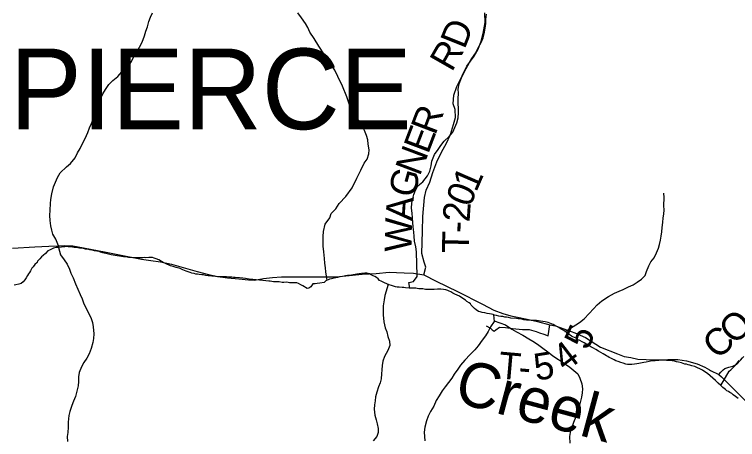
# Model space of a CAD drawing. Extents: x 1310247 to 1664935, y 235267 to 584339.
# Drawn here: x 1460622 to 1468683, y 371649 to 376395 of the extents above; entities that cross this region are included whole.
import ezdxf

# ---------------------------------------------------------------- set-up
doc = ezdxf.new("R2010")
doc.units = 0
for name, color, linetype in [('GM_X_Minor_River', 7, 'Continuous'), ('GM_X_Minor_River_Text', 7, 'Continuous'), ('GM_X_State_Route', 7, 'Continuous'), ('GM_X_Township_Road', 7, 'Continuous'), ('GM_X_Township_Road_Text', 7, 'Continuous'), ('GM_X_Township_Text', 7, 'Continuous')]:
    doc.layers.add(name, color=color, linetype=linetype)

msp = doc.modelspace()

# ---------------------------------------------------------------- linework, layer by layer
at = {"layer": 'GM_X_Minor_River'}
for points in [[(1461120.8, 373794.9), (1461082.9, 373885.9), (1461049.7, 373942.7), (1461036.4, 373987.1), (1461025.2, 374035.5), (1461020.2, 374095.9), (1461017.1, 374150.2), (1461018.1, 374210.4), (1461023.3, 374282.6), (1461026.1, 374328.8), (1461037.2, 374390.9), (1461058.6, 374470.8), (1461100.5, 374574.5), (1461131.5, 374626.2), (1461202.9, 374693.3), (1461247.7, 374730.6), (1461296.9, 374794), (1461326, 374849.8), (1461352.9, 374899.5), (1461384.1, 374961.2), (1461409, 375011), (1461440.2, 375076.8), (1461459.1, 375128.7), (1461480.1, 375178.5), (1461501.1, 375238.4), (1461526.5, 375312.3), (1461585.2, 375459.9), (1461608.1, 375507.7), (1461635, 375557.4), (1461674, 375611), (1461719, 375656.4), (1461773.9, 375703.6), (1461835.4, 375776.9), (1461888.3, 375820.1), (1461923.2, 375863.7), (1461946.1, 375911.5), (1461977, 375961.2), (1462014.3, 376028.8), (1462045.4, 376086.5), (1462070.6, 376156.4), (1462087.5, 376206.3), (1462106.5, 376258.2), (1462119.5, 376316.2), (1462136.4, 376366.1), (1462159.3, 376413.9)], [(1464106.3, 373426.6), (1464093.8, 373521.9), (1464088.6, 373566.1), (1464081.4, 373618.5), (1464076.2, 373668.8), (1464069.5, 373743.2), (1464064.5, 373807.6), (1464063.5, 373865.9), (1464064.3, 373914.1), (1464067.3, 373970.2), (1464086.7, 374052.3), (1464138.1, 374125.7), (1464151, 374171.6), (1464206.1, 374224.9), (1464243.2, 374282.5), (1464314.8, 374363.6), (1464386.7, 374460.8), (1464438.6, 374566.3), (1464484.4, 374657.9), (1464521.8, 374733.6), (1464554.6, 374779.2), (1464571.7, 374837.2), (1464574.5, 374883.3), (1464565.5, 374947.7), (1464560.3, 374996), (1464547.1, 375044.5), (1464523.9, 375099.1), (1464494.8, 375157.9), (1464455.6, 375212.8), (1464412.4, 375269.8), (1464381.3, 375334.6), (1464358.1, 375387.2), (1464327.5, 375476.1), (1464279.3, 375593.5), (1464224.9, 375700.9), (1464192, 375773.8), (1464148.9, 375838.8), (1464121.6, 375885.5), (1464070.6, 375954.7), (1464013.8, 376040), (1463963.1, 376125.3), (1463916.1, 376198.4), (1463892.9, 376249), (1463867.5, 376293.7), (1463822.5, 376358.7), (1463779.2, 376413.7)], [(1465030.5, 373340.8), (1465017.2, 373403.3), (1465071.6, 373414.4), (1465110.7, 373469.9), (1465109.5, 373516.1), (1465108.5, 373574.4), (1465105.8, 373652.8), (1465104.6, 373701), (1465103.3, 373745.2), (1465096.2, 373799.6), (1465083.2, 373864.1), (1465076.1, 373918.4), (1465072.9, 373964.7), (1465065.9, 374025.1), (1465062.6, 374071.3), (1465057.5, 374123.6), (1465054.4, 374177.9), (1465049.3, 374232.3), (1465050.2, 374288.5), (1465061.1, 374338.5), (1465073.9, 374384.5), (1465092.8, 374432.3), (1465119.7, 374480.1), (1465174.7, 374527.3), (1465226, 374594.7), (1465251, 374646.5), (1465268, 374706.5), (1465274.9, 374756.6), (1465304.3, 374832.4), (1465343.4, 374887.9), (1465376.2, 374933.5), (1465413.1, 374979.1), (1465468.2, 375032.4), (1465507.2, 375079.9), (1465532.2, 375133.7), (1465555.1, 375183.5), (1465568.1, 375239.5), (1465573.1, 375297.7), (1465571.9, 375345.9), (1465568.8, 375400.2), (1465567.7, 375452.4), (1465570.7, 375514.6), (1465569.5, 375560.9), (1465580.5, 375618.9), (1465605.7, 375686.8), (1465630.7, 375740.6), (1465655.7, 375790.3), (1465695, 375860), (1465721.8, 375903.7), (1465765, 375967.2), (1465790.1, 376023), (1465823.2, 376082.7), (1465846.1, 376132.5), (1465861.2, 376196.5), (1465868, 376242.6), (1465874.9, 376294.7), (1465877.7, 376338.8), (1465884.7, 376396.9)], [(1466758.8, 372855.4), (1466811.1, 372885.8), (1466922.7, 372956.1), (1466971.6, 372997.5), (1467028.8, 373054.7), (1467077.9, 373108.1), (1467118.7, 373151.6), (1467169.7, 373198.9), (1467244.8, 373247.8), (1467309.6, 373282.8), (1467362.2, 373304), (1467406.7, 373325.3), (1467467.4, 373352.4), (1467518, 373377.6), (1467562.6, 373404.9), (1467611.4, 373438.2), (1467652.2, 373481.7), (1467669, 373525.6), (1467694.2, 373587.4), (1467717, 373633.2), (1467751.9, 373676.8), (1467778.9, 373732.5), (1467799.9, 373784.4), (1467812.6, 373828.4), (1467825.5, 373874.3), (1467832.2, 373918.4), (1467837, 373966.5), (1467843.9, 374014.6), (1467848.8, 374070.8), (1467853.7, 374122.9), (1467860.5, 374167), (1467863.3, 374213.1), (1467862, 374257.3), (1467863.6, 374351.7), (1467862.4, 374400)], [(1463626.1, 373403.5), (1463606.1, 373403.9), (1463574, 373408.4), (1463507.8, 373411.6), (1463473.8, 373416.2), (1463457.8, 373418.5), (1463391.7, 373425.7), (1463353.6, 373428.4), (1463317.5, 373433), (1463279.4, 373435.7), (1463239.3, 373440.4), (1463217.3, 373442.8), (1463197.3, 373447.2), (1463169.3, 373451.7), (1463131.2, 373454.3), (1463083.1, 373459.2), (1463065, 373459.5), (1463045, 373461.9), (1463006.9, 373462.5), (1462984.8, 373465), (1462884.5, 373466.7), (1462862.4, 373469.1), (1462840.4, 373471.5), (1462820.4, 373473.8), (1462782.3, 373478.5), (1462756.2, 373481), (1462728.3, 373487.5), (1462710.2, 373487.8), (1462682.2, 373492.3), (1462662.1, 373494.7), (1462644.1, 373497), (1462626.1, 373501.3), (1462598.1, 373507.9), (1462582.1, 373512.2), (1462558.2, 373522.6), (1462534.2, 373529.1), (1462516.3, 373537.4), (1462500.4, 373543.7), (1462476.5, 373556.2), (1462456.5, 373560.6), (1462440.5, 373566.9), (1462424.5, 373571.2), (1462390.6, 373581.8), (1462360.6, 373588.3), (1462344.6, 373594.7), (1462326.7, 373603), (1462304.8, 373615.4), (1462280.9, 373623.9), (1462259, 373636.3), (1462231.3, 373656.9), (1462201.3, 373667.5), (1462179.4, 373675.9), (1462159.4, 373680.2), (1462141.4, 373682.6), (1462119.3, 373681), (1462087.1, 373679.5), (1462071.1, 373679.8), (1462053, 373678.1), (1462008.8, 373678.9), (1461986.7, 373677.2), (1461940.6, 373678.1), (1461924.5, 373680.3), (1461892.5, 373682.9), (1461860.4, 373687.5), (1461838.4, 373689.9), (1461814.3, 373692.3), (1461766.3, 373701.2), (1461744.3, 373703.6), (1461720.3, 373708), (1461700.3, 373712.4), (1461656.2, 373721.2), (1461608.3, 373734.1), (1461582.3, 373740.6), (1461564.3, 373746.9), (1461538.3, 373751.4), (1461514.3, 373755.8), (1461486.3, 373762.3), (1461460.3, 373766.8), (1461436.3, 373773.3), (1461414.3, 373775.6), (1461390.3, 373782.1), (1461346.2, 373786.9), (1461326.2, 373789.2), (1461302.1, 373791.7), (1461286.1, 373794), (1461268.1, 373798.3), (1461238, 373800.8), (1461222, 373801.1), (1461206, 373803.4), (1461183.9, 373801.8), (1461145.6, 373796.4), (1461119.5, 373794.9), (1461085.3, 373791.5), (1461057.1, 373783.9), (1461026.8, 373772.4), (1461010.6, 373764.6), (1460994.4, 373754.9), (1460965.8, 373725.2), (1460943.3, 373703.5), (1460923, 373687.8), (1460904.6, 373668.1)], [(1461113.7, 373794.3), (1461134.1, 373710.2), (1461177.4, 373657.3), (1461208.7, 373606.5), (1461233.8, 373551.8), (1461251.2, 373507.3), (1461274.3, 373452.7), (1461303.3, 373385.9), (1461326.4, 373329.3), (1461353.5, 373268.5), (1461376.8, 373219.9), (1461390.1, 373175.5), (1461442.5, 373066.1), (1461471.6, 373011.4), (1461490.8, 372954.8), (1461500, 372906.4), (1461506.7, 372830), (1461503.8, 372777.8), (1461497.1, 372733.8), (1461477.9, 372665.8), (1461454.8, 372605.9), (1461427.9, 372558.2), (1461394.9, 372508.6), (1461368.1, 372462.8), (1461342.9, 372399), (1461336.1, 372350.9), (1461337.2, 372296.7), (1461332.4, 372250.5), (1461321.5, 372202.5), (1461300.2, 372128.6), (1461281.3, 372076.7), (1461262.4, 372030.8), (1461239.2, 371960.9), (1461226.4, 371917), (1461219.1, 371842.8), (1461220.2, 371788.5), (1461215.1, 371726.3), (1461210.4, 371682.2), (1461213.5, 371628)], [(1460904.6, 373668.1), (1460880.1, 373642.4), (1460875.8, 373626.4), (1460847.3, 373602.8), (1460830.8, 373579), (1460816.5, 373561.2), (1460799.9, 373533.3), (1460789.6, 373515.4), (1460777.3, 373497.6), (1460766.9, 373479.7), (1460750.4, 373453.8), (1460736, 373432), (1460717.6, 373410.2), (1460697.2, 373392.5), (1460668.9, 373383), (1460636.7, 373377.5), (1460618.6, 373371.8)], [(1466257, 372995.9), (1466238.9, 372998.2), (1466216.9, 373000.6), (1466156.8, 373005.7), (1466128.7, 373010.2), (1466106.7, 373014.6), (1466086.7, 373017), (1466066.7, 373021.3), (1466044.6, 373023.7), (1466020.6, 373028.2), (1465996.7, 373034.6), (1465974.6, 373039), (1465956.7, 373043.4), (1465940.7, 373047.6), (1465918.7, 373052), (1465892.6, 373056.5), (1465864.6, 373063), (1465836.6, 373067.6), (1465812.6, 373074), (1465794.7, 373080.3), (1465768.9, 373098.9), (1465751.1, 373113.2), (1465731.3, 373131.7), (1465713.5, 373148), (1465705.8, 373164.2), (1465689.9, 373174.6), (1465664.1, 373191.1), (1465648.2, 373205.4), (1465630.4, 373217.8), (1465582.7, 373248.8), (1465531, 373273.8), (1465509.1, 373284.2), (1465487.2, 373296.6), (1465467.3, 373307), (1465451.3, 373313.3), (1465431.4, 373319.7), (1465405.3, 373324.2), (1465375.3, 373326.7), (1465337.1, 373327.4), (1465301, 373326), (1465268.8, 373324.5), (1465242.7, 373323), (1465226.7, 373323.3), (1465204.6, 373325.7), (1465172.6, 373330.2), (1465150.5, 373330.6), (1465128.5, 373333), (1465110.4, 373335.4), (1465094.4, 373337.6), (1465076.4, 373338), (1465058.3, 373340.3), (1465020.2, 373341), (1464982.1, 373343.6), (1464964.1, 373346), (1464944, 373346.3), (1464909.9, 373348.9), (1464887.9, 373351.3), (1464867.9, 373355.7), (1464826, 373368.5), (1464800, 373376.9), (1464748.2, 373397.9), (1464730.2, 373406.3), (1464708.3, 373416.7), (1464692.4, 373425), (1464676.7, 373443.4), (1464658.9, 373459.8), (1464640.9, 373468.1), (1464621.1, 373478.5), (1464599.1, 373488.9), (1464581.3, 373499.3), (1464551.3, 373507.8), (1464529.2, 373506.2), (1464491, 373502.9), (1464438.6, 373493.7), (1464380.3, 373484.7), (1464336, 373479.5), (1464311.9, 373475.9), (1464295.7, 373472.1), (1464277.7, 373470.5), (1464247.4, 373464.9), (1464221.2, 373457.4), (1464187, 373449.9), (1464156.7, 373442.4), (1464134.6, 373438.8), (1464094.2, 373421.4), (1464075.8, 373403.7), (1464025.5, 373394.5), (1463997.3, 373391), (1463973.1, 373387.4), (1463947.1, 373387.8), (1463924.4, 373354.1), (1463902.1, 373338.4), (1463885.9, 373334.7), (1463836.3, 373365.7), (1463814.4, 373376.1), (1463786.6, 373392.7), (1463770.6, 373397), (1463724.4, 373399.8), (1463688.3, 373400.4), (1463656.3, 373405), (1463626.1, 373403.5)], [(1464787.7, 373381.9), (1464751.8, 373257.3), (1464742.9, 373207.2), (1464733.8, 373143.1), (1464730.9, 373090.9), (1464732.1, 373040.7), (1464738.8, 372962.2), (1464753.8, 372895.7), (1464771.1, 372851.2), (1464784.2, 372798.7), (1464803.4, 372746.2), (1464804.6, 372698), (1464785.6, 372644.1), (1464748.4, 372576.4), (1464727.4, 372524.6), (1464722.6, 372474.4), (1464717.8, 372428.3), (1464715, 372382.2), (1464708.1, 372328.1), (1464697.3, 372284), (1464680.5, 372238.1), (1464661.4, 372178.2), (1464646.4, 372126.3), (1464641.7, 372080.1), (1464636.9, 372036), (1464630.1, 371990), (1464639, 371921.5), (1464654.2, 371871), (1464665.5, 371824.6), (1464676.7, 371774.2), (1464675.9, 371728), (1464661.1, 371684.1), (1464620.1, 371634.6)], [(1465961.6, 373042.2), (1465969.4, 372966.8), (1465930.3, 372907.2), (1465901.3, 372855.5), (1465872.4, 372805.8), (1465837.4, 372758.2), (1465790.2, 372694.8), (1465755.3, 372651.2), (1465702.2, 372597.9), (1465643, 372536.7), (1465593.8, 372479.3), (1465563, 372433.6), (1465521.9, 372378.1), (1465497.1, 372334.3), (1465462.1, 372284.7), (1465423.2, 372239.2), (1465388.3, 372191.6), (1465357.2, 372135.9), (1465324.2, 372084.3), (1465295.1, 372022.5), (1465260, 371962.9), (1465233, 371909.1), (1465216.1, 371859.2), (1465196.8, 371789.2), (1465189.8, 371731.1), (1465191, 371682.9), (1465198.2, 371634.5)], [(1468688.9, 372105.7), (1468661.3, 372130.3), (1468635.5, 372148.8), (1468617.6, 372163.2), (1468597.7, 372173.6), (1468581.9, 372183.9), (1468564, 372194.3), (1468548.1, 372206.6), (1468520.4, 372231.2), (1468494.7, 372253.8), (1468467.1, 372280.3), (1468435.4, 372309), (1468405.8, 372335.6), (1468346.4, 372384.9), (1468316.6, 372405.5), (1468290.8, 372422), (1468261, 372438.6), (1468235.1, 372451.1), (1468205.2, 372463.7), (1468173.2, 372472.3), (1468151.2, 372478.7), (1468131.2, 372483.1), (1468113.3, 372489.4), (1468095.2, 372491.7), (1468059.4, 372506.4), (1468025.3, 372513), (1468003.3, 372517.5), (1467979.4, 372523.9), (1467955.3, 372528.3), (1467925.3, 372530.9), (1467891.2, 372531.5), (1467857.1, 372534.1), (1467831, 372534.5), (1467806.9, 372532.9), (1467762.7, 372529.7), (1467728.5, 372526.3), (1467696.3, 372520.8), (1467664, 372513.3), (1467639.9, 372509.8), (1467581.5, 372498.7), (1467559.3, 372495.1), (1467535.2, 372489.5), (1467505, 372488), (1467484.9, 372486.3), (1467456.8, 372486.8), (1467438.8, 372489.2), (1467406.9, 372501.8), (1467380.9, 372510.3), (1467353, 372518.8), (1467327.1, 372529.3), (1467307.1, 372537.7), (1467271.3, 372556.4), (1467253.4, 372564.7), (1467237.5, 372575), (1467221.6, 372583.3), (1467203.7, 372593.7), (1467183.8, 372606.1), (1467160, 372620.6), (1467132.1, 372635.1), (1467104.3, 372653.7), (1467076.5, 372670.2), (1467048.6, 372684.8), (1467024.8, 372699.3), (1467006.9, 372709.6), (1466991, 372717.9), (1466973.1, 372730.3), (1466957.2, 372736.6), (1466917.4, 372757.4), (1466901.4, 372763.7), (1466883.6, 372780.1), (1466847.8, 372794.8), (1466831.9, 372805.1), (1466816, 372815.4), (1466796.2, 372829.8), (1466772.3, 372846.3), (1466744.5, 372864.9), (1466724.7, 372877.3), (1466683, 372904.1), (1466647.2, 372922.8), (1466627.3, 372935.2), (1466589.4, 372947.9), (1466571.4, 372954.3), (1466539.5, 372964.9), (1466485.4, 372971.8), (1466441.4, 372978.6), (1466381.1, 372979.7), (1466331, 372982.6), (1466301, 372987.1), (1466277, 372993.6), (1466257, 372995.9)], [(1465968.6, 372974.5), (1466097.3, 372930.4), (1466166.7, 372881), (1466218.4, 372852), (1466288, 372814.6), (1466355.6, 372775.3), (1466401.3, 372748.3), (1466451, 372715.3), (1466510.4, 372668.1), (1466567.9, 372626.9), (1466619.4, 372587.9), (1466669.1, 372554.8), (1466714.7, 372523.9), (1466764.3, 372490.9), (1466812, 372458), (1466859.5, 372421), (1466903, 372382), (1466924.3, 372333.5), (1466945.3, 372270.8), (1466954.4, 372214.4), (1466951.7, 372170.3), (1466944.8, 372122.2), (1466912.7, 372002.2), (1466893.7, 371946.3), (1466878.9, 371902.4), (1466853.7, 371838.6), (1466838.9, 371794.6), (1466822.1, 371748.7), (1466811, 371682.6), (1466813.7, 371608.3)], [(1468497.5, 372251.3), (1468589.7, 372410.8), (1468608, 372426.5), (1468626.4, 372444.3), (1468644.8, 372464), (1468661.1, 372479.8), (1468681.6, 372505.6), (1468700.2, 372533.4)]]:
    msp.add_lwpolyline(points, dxfattribs=at)
at = {"layer": 'GM_X_State_Route'}
for points in [[(1460598.3, 373783.9), (1460849.8, 373801.8), (1461006.5, 373806.2), (1461120.8, 373812.5), (1461181.8, 373815.2), (1461272.4, 373812.9), (1461392, 373790.6), (1461626.7, 373743.6), (1461886.1, 373693.3), (1462038.1, 373664.3), (1462143.2, 373648.6), (1462248.3, 373631.9), (1462372.3, 373608.4), (1462503.1, 373571.5), (1462657.4, 373523.4), (1462786, 373492.1), (1462889.9, 373469.8), (1462995, 373456.3), (1463124.7, 373442.9), (1463230.9, 373432.9), (1463297.7, 373429.3), (1463398.5, 373447.4), (1463498, 373459.7), (1463597.5, 373465.3), (1463680.2, 373466.4), (1463805.4, 373465.3), (1463887.1, 373464.2), (1464071.5, 373465.3), (1464207.9, 373465.3), (1464354.3, 373482.1), (1464499.6, 373496.6), (1464655.7, 373501.3), (1464797.1, 373518.1), (1464879.2, 373515.4), (1464965.1, 373510.5), (1465072, 373507.8), (1465184.5, 373489.7), (1465323.5, 373416.1), (1465560.5, 373302.1), (1465839.9, 373160.1), (1465965.1, 373095.3), (1466064.7, 373057.3), (1466155.2, 373029.3), (1466229, 373014.8), (1466336.5, 372993.1), (1466454.1, 372967.2), (1466590.5, 372931.4), (1466651.5, 372917.4), (1466747, 372884), (1466869.7, 372841.7), (1466987, 372787.9), (1467153.3, 372681.5), (1467342.9, 372605.2), (1467419.2, 372577.9), (1467493.7, 372564), (1467569.6, 372547.2), (1467757.6, 372538.9), (1467906.4, 372541.8), (1468017.3, 372542.9), (1468112.5, 372528.8), (1468231.5, 372493.6), (1468316.5, 372457.4), (1468371.1, 372427.1), (1468382.1, 372421.6)], [(1468382.1, 372421.6), (1468476, 372374.1), (1468503.6, 372347.6), (1468584.8, 372268.6), (1468748.7, 372104.7), (1468909.9, 371946.8), (1469073.2, 371823.4), (1469203.6, 371718.5), (1469325.8, 371621.7)]]:
    msp.add_lwpolyline(points, dxfattribs=at)
at = {"layer": 'GM_X_Township_Road'}
for points in [[(1465184.5, 373489.7), (1465208.3, 373573.1), (1465189, 373631), (1465162.2, 373726.1), (1465171.2, 373977.2), (1465172.6, 374140.6), (1465192, 374350.1), (1465211.2, 374433.3), (1465252.8, 374522.4), (1465285.6, 374630.9), (1465331.6, 374749.7), (1465386.6, 374865.7), (1465432.6, 374951.8), (1465481.6, 375055.8), (1465517.3, 375167.2), (1465536.6, 375243), (1465535.1, 375333.6), (1465512.8, 375396), (1465518.8, 375494.1), (1465553, 375592.2), (1465613.9, 375711), (1465664.4, 375818), (1465746.8, 375930.5), (1465789.7, 376005.9), (1465825.2, 376097.5), (1465847.3, 376183.2), (1465869.5, 376305.8), (1465865, 376413.7)], [(1465881.1, 372918.8), (1465927.4, 372890.9), (1465946.5, 372873.8), (1465967.7, 372858.1), (1465986.7, 372874.5), (1466029.7, 372903.8), (1466095.2, 372900.4), (1466174.9, 372888.1), (1466284.7, 372877.2), (1466360.4, 372877.9), (1466437.4, 372854.7), (1466476.3, 372841.7), (1466524, 372824.7), (1466571, 372807), (1466590.5, 372931.4)], [(1468476, 372374.1), (1468498.2, 372400.6), (1468521.5, 372426.6), (1468542, 372441.2), (1468584.6, 372456.9), (1468630.2, 372468.2), (1468675.6, 372491), (1468717.5, 372536.2), (1468739.5, 372561.1), (1468754.5, 372576.2)]]:
    msp.add_lwpolyline(points, dxfattribs=at)

# ---------------------------------------------------------------- texts
at = {"layer": 'GM_X_Minor_River_Text'}
msp.add_text('Creek', height=500, rotation=344.99696, dxfattribs=at).set_placement((1465505.2, 372075))
at = {"layer": 'GM_X_Township_Road_Text'}
for s, rotation, p in [('D', 68.13635, (1465638.9, 375997.2)), ('R', 60.17621, (1465496.9, 375743.2)), ('R', 69.21692, (1465312.5, 375037.4)), ('E', 69.22124, (1465232.9, 374827.6)), ('N', 69.31818, (1465139.7, 374580.8)), ('G', 74.5765, (1465071.7, 374333.2)), ('1', 66.58069, (1465768.8, 374401.5)), ('0', 68.30489, (1465701.4, 374232)), ('A', 86.07009, (1465056.3, 374085.5)), ('2', 86.29219, (1465694.9, 374071.7)), ('W', 88.57778, (1465047.8, 373741.4)), ('-', 88.34491, (1465691.5, 373951.4)), ('T', 88.70564, (1465686.4, 373727.6)), ('O', 41.99262, (1468643.9, 372698)), ('5', 65.70318, (1467011.8, 372635.2)), ('C', 42.11747, (1468461.3, 372532.9)), ('4', 37.41942, (1466765.7, 372397.7)), ('T', 354.99377, (1466009.7, 372332.6)), ('5', 9.13566, (1466436.4, 372305.2)), ('-', 354.99377, (1466233.2, 372313))]:
    msp.add_text(s, height=300, rotation=rotation, dxfattribs=at).set_placement(p)
at = {"layer": 'GM_X_Township_Text'}
msp.add_text('PIERCE', height=900, rotation=0.00001, dxfattribs=at).set_placement((1460569.7, 375113.9))

doc.saveas('drawing.dxf')
